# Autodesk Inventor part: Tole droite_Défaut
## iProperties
Shininess: 64.0
Length Units: 11269
Angle Units: 11279
Time Units: 11290
Mass Units: 11283
Length Display Precision: 3
Angle Display Precision: 2
Compacted: True
Part Number: Tole droite_Défaut
Document SubType Name: Modeling
Created: 2006-01
Material: Par défaut
Designer: Fricot
Density: 0.0
Volumn: 0.0
Area: 0.0
PropertySet Name: Model Information
Control State: 0
Master: False
Checked Out: False
Author: Fricot
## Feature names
1. Base1
